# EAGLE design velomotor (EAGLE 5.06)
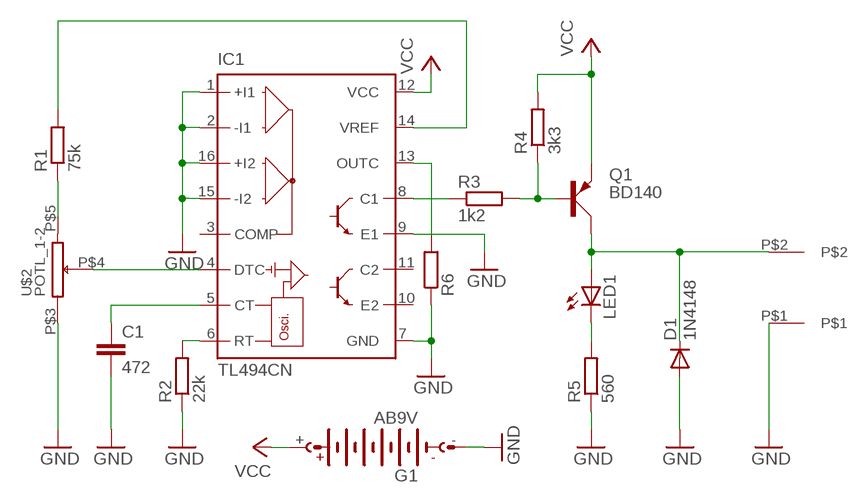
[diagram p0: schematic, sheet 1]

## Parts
C1  472  C-EU050-024X044  [C050-024X044]
D1  1N4148  [DO35-10]
G1  AB9V  [AB9V]
IC1  TL494CN  [DIL16]
LED1  LED3MM  [LED3MM]
Q1  BD140  [TO126AV]
R1  75k  R-EU_0207/10  [0207/10]
R2  22k  R-EU_0207/10  [0207/10]
R3  1k2  R-EU_0207/10  [0207/10]
R4  3k3  R-EU_0207/10  [0207/10]
R5  560  R-EU_0207/10  [0207/10]
R6  R-EU_0207/10  [0207/10]
U$1  JACK  [JACK1]
U$2  POTL_1-2  [POTL_1-2]

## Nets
GND: C1.2 D1.A G1.- IC1.1(+I1) IC1.2(-I1) IC1.7(GND) IC1.9(E1) IC1.15(-I2) IC1.16(+I2) R2.1 R5.1 R6.1 U$1.P$1 U$2.P$3
N$1: IC1.13(OUTC) R6.2
N$2: IC1.14(VREF) R1.2
N$3: R1.1 U$2.P$5
N$4: IC1.4(DTC) U$2.P$4
N$5: C1.1 IC1.5(CT)
N$6: IC1.6(RT) R2.2
N$7: IC1.8(C1) R3.1
N$8: Q1.B R3.2 R4.1
N$9: D1.C LED1.A Q1.C U$1.P$2
N$10: LED1.K(C) R5.2
VCC: G1.+ IC1.12(VCC) Q1.E R4.2
Unconnected: IC1.3(COMP) IC1.10(E2) IC1.11(C2)

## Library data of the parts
C1 = rcl:C-EU: CAPACITOR, European symbol
D1 = diode:1N4148: DIODE
G1 = battery:AB9V: 9-V BATTERY CLIP
IC1 = linear:TL494*: SWITCHMODE Pulse Width Modulation Control Circuit NCV494B http://onsemi.com tl494-d.pdf
LED1 = led:LED: LED
Q1 = transistor-power:BD140: PNP TRANSISTOR
R1-R6 = rcl:R-EU_: RESISTOR, European symbol
U$1 = jack:JACK
U$2 = Pot1:POTL_1-2

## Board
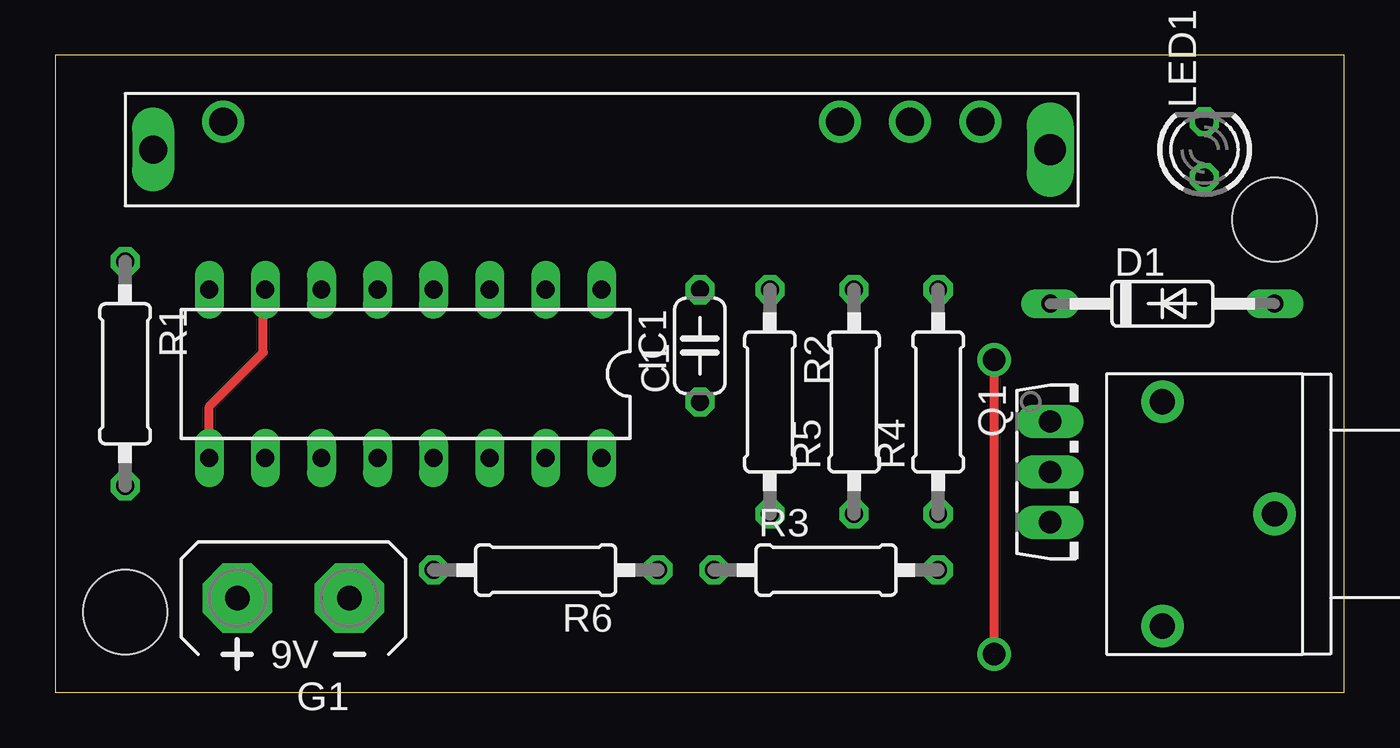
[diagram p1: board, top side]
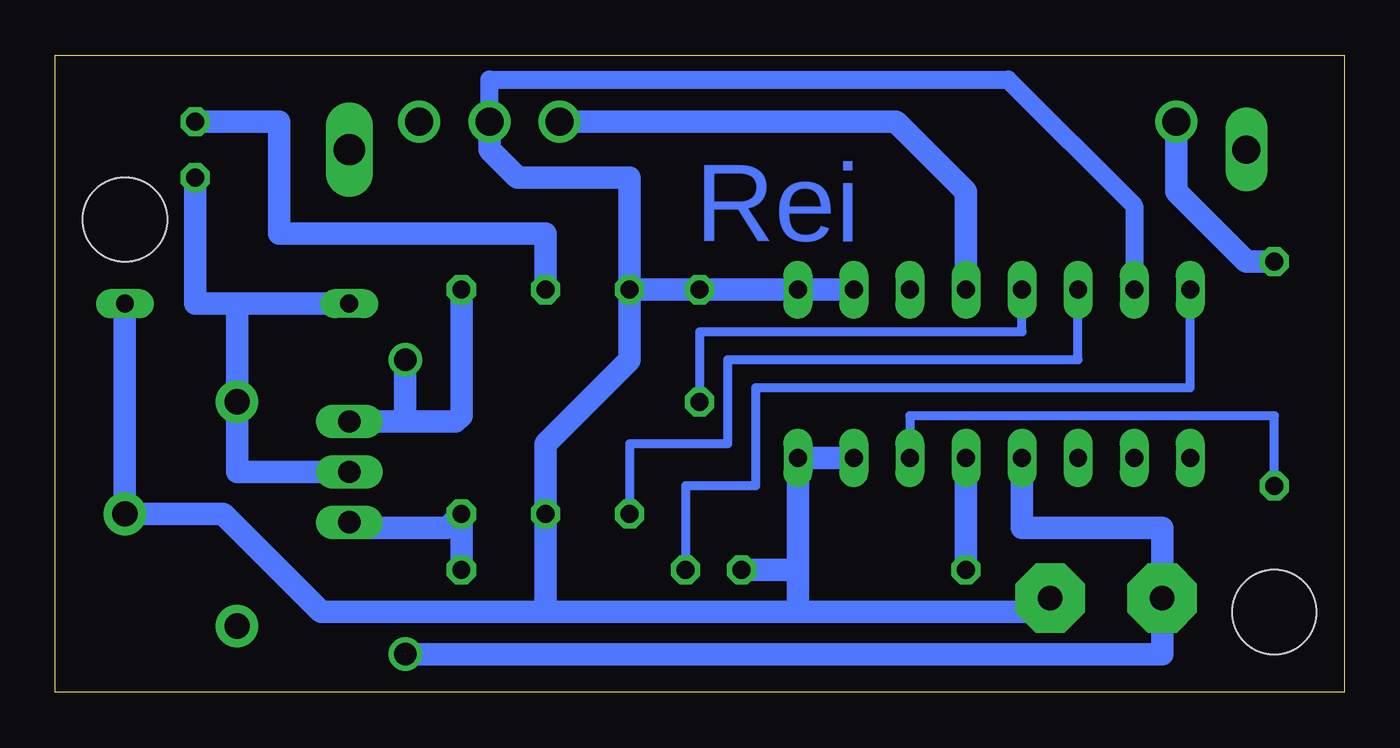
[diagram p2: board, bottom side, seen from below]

Size 58.4 x 28.88 mm. Coordinates in mm from the lower left corner, seen from the top.
Outline: 0,0 58.4,0 58.4,28.88 0,28.88 0,0
Copper layers (1*16): Top 0.035mm / dielectric 1.5mm / Bottom 0.035mm
Design rules "default": minimum track width 10mil, minimum drill 24mil, track to track 8mil, track to pad 8mil, pad to pad 8mil, via to via 8mil, smd to smd 8mil, copper to edge 40mil, drill to drill 8mil, minimum pad ring 10mil, minimum via ring 8mil, stop-mask expansion 4mil, vias tented up to drill 0mil, thermal gap 10mil
Holes 3.81 mm at 3.17,3.64 55.24,21.42

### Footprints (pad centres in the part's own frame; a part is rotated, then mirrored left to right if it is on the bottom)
C050-024X044 = drill 0.813 octagon: 1 -2.54,0; 2 2.54,0
DO35-10 = drill 0.813 long: A 5.08,0; C -5.08,0
AB9V = drill 1.118 pad 3.15 octagon: + 0,2.54; - 0,-2.54
DIL16 = drill 0.813 long: 1 -8.89,-3.81; 2 -6.35,-3.81; 3 -3.81,-3.81; 4 -1.27,-3.81; 5 1.27,-3.81; 6 3.81,-3.81; 7 6.35,-3.81; 8 8.89,-3.81; 9 8.89,3.81; 10 6.35,3.81; 11 3.81,3.81; 12 1.27,3.81; 13 -1.27,3.81; 14 -3.81,3.81; 15 -6.35,3.81; 16 -8.89,3.81
LED3MM = drill 0.813 octagon: A -1.27,0; K 1.27,0
TO126AV = drill 1.016 long: B 2.286,-1.27; C 0,-1.27; E -2.286,-1.27
0207/10 = drill 0.813 octagon: 1 -5.08,0; 2 5.08,0
JACK1 = drill 1.143 pad 1.93 round: P$1 0,3.81; P$2 -5.08,-1.27; P$3 5.08,-1.27
POTL_1-2 = drill 1.422 long: P$1 -21.59,0 | drill 1.27 round: P$2 -18.415,-1.27; P$3 -15.24,-1.27; P$4 -12.065,-1.27; P$5 15.875,-1.27 | drill 1.27 long: P$6 19.05,0

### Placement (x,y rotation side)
C1  29.2,15.71 90 top
D1  50.16,17.61 0 top
G1  10.79,4.28 90 top
IC1  15.87,14.44 180 top
LED1  52.07,24.6 90 top
Q1  46.35,9.99 270 top
R1  3.17,14.44 270 top
R2  32.38,13.17 270 top
R3  34.92,5.55 0 top
R4  40,13.17 90 top
R5  36.19,13.17 90 top
R6  22.22,5.55 180 top
U$1  51.43,8.09 270 top
U$2  23.49,24.6 180 top

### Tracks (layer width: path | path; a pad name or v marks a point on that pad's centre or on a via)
GND
  Top 0.406: IC1.9 6.98,12.96 9.43,15.41 9.43,18.16 IC1.7
  Bottom 0.813: IC1.7 9.52,22.06 15.23,27.77 38.73,27.77 U$2.P$3
  Bottom 1.016: IC1.2 IC1.1 C1.2 R2.1 | U$2.P$3 38.73,24.6 37.46,23.33 32.38,23.33 R2.1 | IC1.15 IC1.16 24.76,5.55 | R2.1 32.38,15.08 36.19,11.27 R5.1 36.19,3.64 | 24.76,3.64 24.76,5.55 | 24.76,3.64 36.19,3.64 | 24.76,5.55 R6.1 | G1.- 13.33,3.64 24.76,3.64 | 36.19,3.64 46.35,3.64 50.8,8.09 U$1.P$1 D1.A
N$1
  Bottom 1.016: R6.2 IC1.13
N$2
  Bottom 0.406: R1.2 3.17,12.53 19.68,12.53 IC1.14
N$3
  Bottom 1.016: R1.1 4.44,19.52 7.61,22.69 U$2.P$5
N$4
  Bottom 1.016: U$2.P$4 20.31,25.87 17.14,22.69 IC1.4
N$5
  Bottom 0.406: C1.1 29.2,16.34 14.6,16.34 IC1.5
N$6
  Bottom 0.406: IC1.6 12.06,15.08 27.94,15.08 27.94,11.27 32.38,11.27 R2.2
N$7
  Bottom 0.406: IC1.8 6.98,13.8 26.66,13.8 26.66,9.36 29.84,9.36 R3.1
N$8
  Bottom 1.016: R3.2 R4.1 40.63,7.45 45.08,7.45 Q1.B
N$9
  Bottom 1.016: LED1.A 52.07,17.61 50.16,17.61 | 50.16,17.61 D1.C | 50.16,17.61 U$1.P$2 50.16,9.99 Q1.C
N$10
  Bottom 1.016: R5.2 36.19,20.79 48.26,20.79 48.26,25.87 LED1.K
N$11  (via drill 1.02)
  other vias: 42.54,15.08
N$13  (via drill 1.02)
  other vias: 42.54,1.74
VCC  (via drill 1.02)  (1 unrouted)
  Top 0.406: 42.54,1.74 v42.54,15.08
  Bottom 1.016: R4.2 40,12.53 40.25,12.28 Q1.E 42.54,12.28 v42.54,15.08 | 8.25,7.45 G1.+ | IC1.12 14.6,7.45 8.25,7.45 | 8.25,7.45 8.25,1.74 42.54,1.74

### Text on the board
Bottom: Rei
